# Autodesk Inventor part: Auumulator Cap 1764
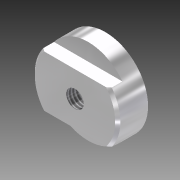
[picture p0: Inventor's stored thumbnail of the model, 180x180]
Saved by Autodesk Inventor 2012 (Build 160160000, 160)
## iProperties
Created: 2010-01
Part Number: Auumulator Cap 1764
Document SubType Name: Modeling
Designer: cmcfadden
Density: 1 g/cm^3
Material: Default
Author: cmcfadden
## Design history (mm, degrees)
sketch "Sketch1"
  geometry: C1 r 26.441 at (-14.977, 17.358); 1 further point
  constraints: 1 centre point
  dimensions: "d0" = 52.8828 diameter of C1
extrude "Extrusion1" new body sketch "Sketch1" distance "d1" = 18.7198; taper "d2" = 0 deg
chamfer "Chamfer1" distance "d3" = 1.5875; stored, may be unused: second distance "d4" = 3.175, angle "d5" = 45 deg
sketch "Sketch2"
  geometry: L1 (-21.145, -15.875)-(21.145, -15.875); L2 (-21.145, 15.875)-(21.145, 15.875); C1 r 24.854 at (0, 0) reference; A1 r 26.441 centre (0, 0) between (-21.145, -15.875) and (21.145, -15.875) reference; A2 r 26.441 centre (0, 0) between (21.145, 15.875) and (-21.145, 15.875); A3 r 26.441 centre (0, 0) between (-21.145, -15.875) and (21.145, -15.875); 1 further point
  constraints: 8 point on circle, 4 end point, 2 centre point, 2 concentric, 1 horizontal
  dimensions: "d6" = 31.75 distance between parallel lines of L1 L2; "d7" = 15.875 distance from line of C1.centre L2
extrude "Extrusion2" cut sketch "Sketch2" distance "d8" = 8.128; taper "d9" = 0 deg
sketch "Sketch3"
  geometry: C1 r 5.397 at (-14.977, 17.358); A1 r 24.854 centre (-14.977, 17.358) between (-34.1, 33.233) and (-34.1, 1.483) reference; 1 further point
  constraints: 1 centre point, 1 coincident
  dimensions: "d10" = 10.795 diameter of C1
extrude "Extrusion3" cut sketch "Sketch3" stored distance "d11" = 8.128; taper "d12" = 0 deg
thread "Thread1" dims "d13" = 25.4, "d14" = 0
body "Solid1"
